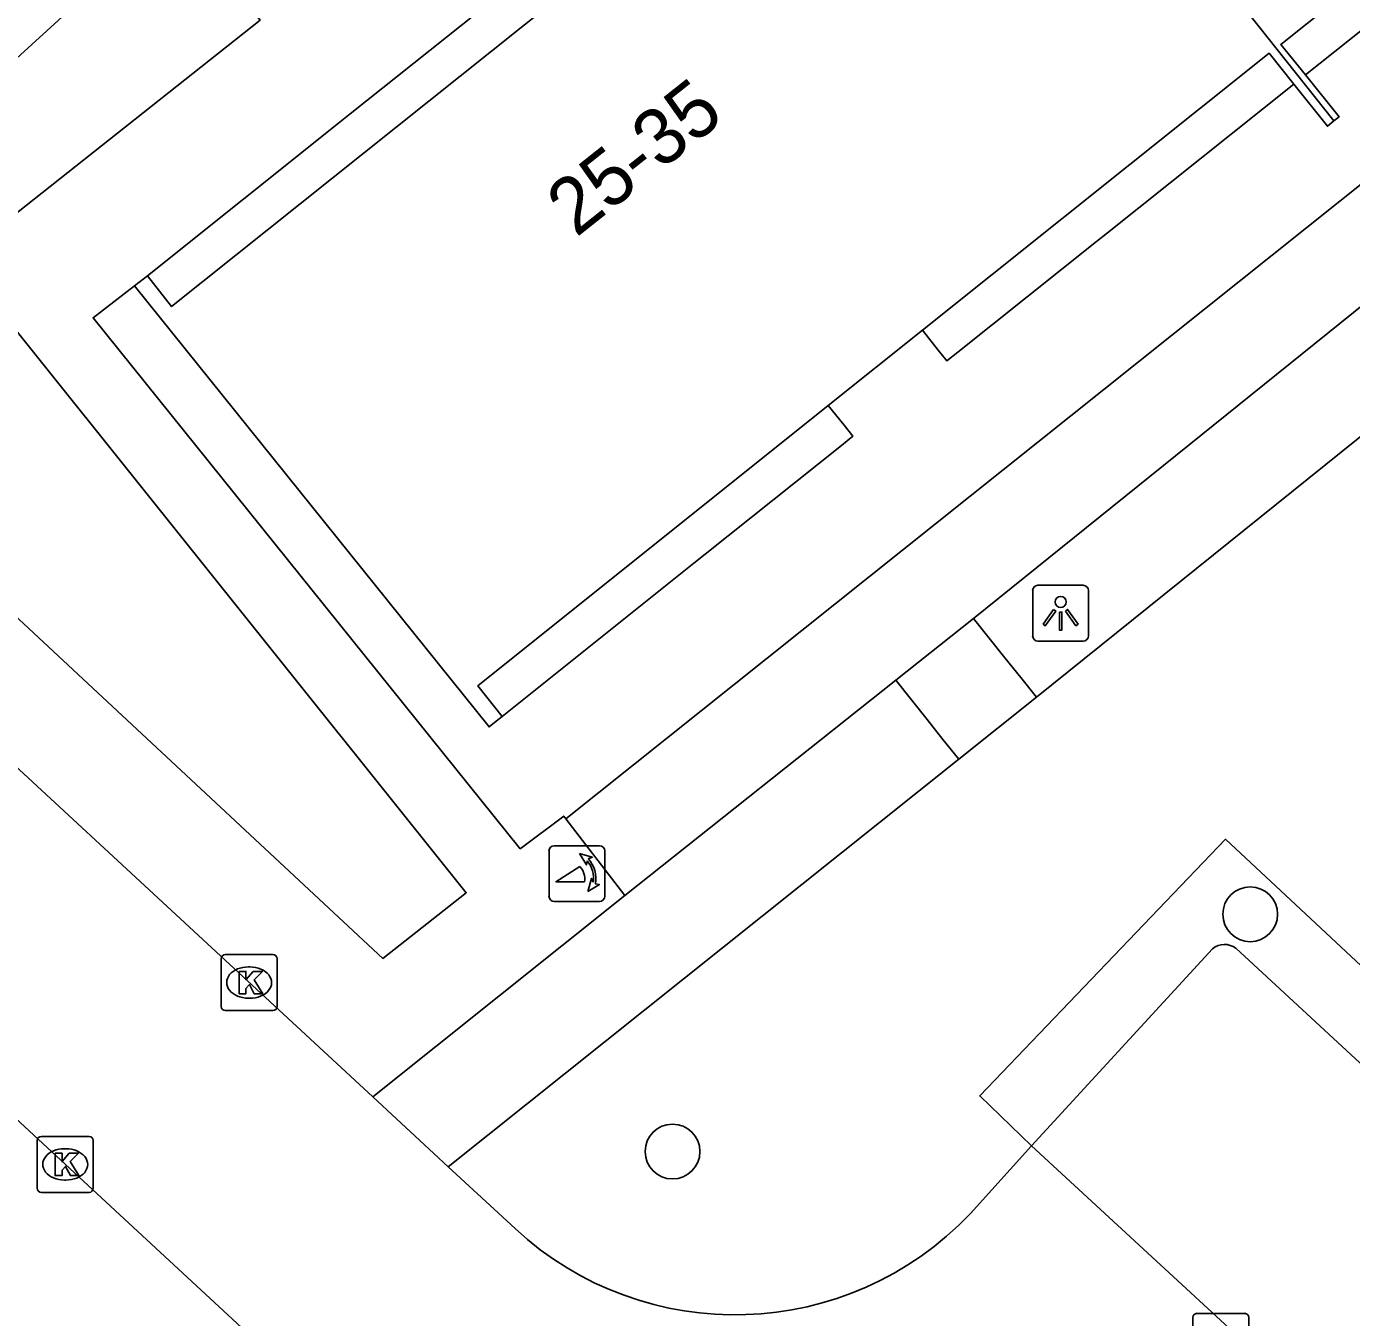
# Model space of a CAD drawing. Extents: x 159040 to 160094, y 381214 to 382518.
# Drawn here: x 159732.63 to 159756.29, y 381881.89 to 381904.94 of the extents above; entities that cross this region are included whole.
import ezdxf

# ---------------------------------------------------------------- set-up
doc = ezdxf.new("R2010")
doc.units = 0
for name, color, linetype in [('IMGEO_Boom', 7, 'Continuous'), ('IMGEO_Haag', 7, 'Continuous'), ('IMGEO_Kolk', 7, 'Continuous'), ('IMGEO_Lichtpunt', 7, 'Continuous'), ('IMGEO_Pand', 7, 'Continuous'), ('IMGEO_Pand_nummerreeks', 7, 'Continuous'), ('IMGEO_Pand_overbouw', 7, 'Continuous'), ('IMGEO_Parkeervlak_open', 7, 'Continuous'), ('IMGEO_Poller', 7, 'Continuous'), ('IMGEO_Rijbaan_lokaal_open', 7, 'Continuous'), ('IMGEO_Voetpad_gesloten', 7, 'Continuous'), ('IMGEO_Voetpad_open', 7, 'Continuous')]:
    doc.layers.add(name, color=color, linetype=linetype)

msp = doc.modelspace()

# ---------------------------------------------------------------- linework, layer by layer
at = {"layer": 'IMGEO_Boom'}
for centre in [(159754.484, 381889.092), (159744.169, 381884.857)]:
    msp.add_circle(centre, 0.489, dxfattribs=at)
at = {"layer": 'IMGEO_Haag'}
for points in [[(159763.551, 381903.327), (159750.668, 381892.968)], [(159749.281, 381891.862), (159740.163, 381884.586)], [(159767.12, 381878.228), (159754.045, 381890.43), (159749.655, 381885.849), (159750.578, 381884.958)]]:
    msp.add_lwpolyline(points, dxfattribs=at)
at = {"layer": 'IMGEO_Kolk'}
for p, q in [((159736.109, 381887.447), (159736.109, 381888.299)), ((159736.184, 381888.373), (159737.036, 381888.373)), ((159737.11, 381888.299), (159737.11, 381887.447)), ((159736.597, 381888.153), (159736.622, 381888.153)), ((159736.62, 381887.593), (159736.595, 381887.593)), ((159737.036, 381887.373), (159736.184, 381887.373)), ((159732.825, 381884.201), (159732.825, 381885.053)), ((159732.9, 381885.127), (159733.752, 381885.127)), ((159733.826, 381885.053), (159733.826, 381884.201)), ((159733.313, 381884.907), (159733.338, 381884.907)), ((159733.336, 381884.347), (159733.311, 381884.347)), ((159733.752, 381884.127), (159732.9, 381884.127)), ((159753.458, 381881.042), (159753.458, 381881.894)), ((159753.533, 381881.968), (159754.385, 381881.968)), ((159754.459, 381881.894), (159754.459, 381881.042))]:
    msp.add_line(p, q, dxfattribs=at)
for points in [[(159736.109, 381887.447), (159736.109, 381888.299)], [(159736.184, 381888.373), (159737.036, 381888.373)], [(159737.11, 381888.299), (159737.11, 381887.447)], [(159736.43, 381888.073), (159736.553, 381888.073), (159736.553, 381887.922), (159736.683, 381888.073), (159736.847, 381888.073), (159736.701, 381887.922), (159736.854, 381887.673), (159736.702, 381887.673), (159736.617, 381887.837), (159736.553, 381887.77), (159736.553, 381887.673), (159736.43, 381887.673), (159736.43, 381888.073)], [(159737.036, 381887.373), (159736.184, 381887.373)], [(159732.825, 381884.201), (159732.825, 381885.053)], [(159732.9, 381885.127), (159733.752, 381885.127)], [(159733.826, 381885.053), (159733.826, 381884.201)], [(159733.146, 381884.827), (159733.269, 381884.827), (159733.269, 381884.676), (159733.399, 381884.827), (159733.563, 381884.827), (159733.417, 381884.676), (159733.57, 381884.427), (159733.418, 381884.427), (159733.333, 381884.591), (159733.269, 381884.524), (159733.269, 381884.427), (159733.146, 381884.427), (159733.146, 381884.827)], [(159733.752, 381884.127), (159732.9, 381884.127)], [(159753.458, 381881.042), (159753.458, 381881.894)], [(159753.533, 381881.968), (159754.385, 381881.968)], [(159754.459, 381881.894), (159754.459, 381881.042)]]:
    msp.add_lwpolyline(points, dxfattribs=at)
for centre, start, end in [((159736.186, 381888.297), 91.552, 178.448), ((159736.186, 381888.297), 91.552, 178.448), ((159737.034, 381888.297), 1.552, 88.448), ((159737.034, 381888.297), 1.552, 88.448), ((159736.186, 381887.449), 181.552, 268.448), ((159736.186, 381887.449), 181.552, 268.448), ((159737.034, 381887.449), 271.552, 358.448), ((159737.034, 381887.449), 271.552, 358.448), ((159732.902, 381885.051), 91.552, 178.448), ((159732.902, 381885.051), 91.552, 178.448), ((159733.75, 381885.051), 1.552, 88.448), ((159733.75, 381885.051), 1.552, 88.448), ((159732.902, 381884.203), 181.552, 268.448), ((159732.902, 381884.203), 181.552, 268.448), ((159733.75, 381884.203), 271.552, 358.448), ((159733.75, 381884.203), 271.552, 358.448), ((159753.535, 381881.892), 91.552, 178.448), ((159753.535, 381881.892), 91.552, 178.448), ((159754.383, 381881.892), 1.552, 88.448), ((159754.383, 381881.892), 1.552, 88.448)]:
    msp.add_arc(centre, 0.0765, start, end, dxfattribs=at)
for centre, major_axis, ratio, start_param, end_param in [((159736.596, 381887.873), (-0.387, 0.002), 0.722429, 4.712389, 7.853982), ((159736.621, 381887.873), (-0.39, 0.002), 0.717154, 1.570796, 4.712389), ((159733.312, 381884.627), (-0.387, 0.002), 0.722429, 4.712389, 7.853982), ((159733.337, 381884.627), (-0.39, 0.002), 0.717154, 1.570796, 4.712389)]:
    msp.add_ellipse(centre, major_axis=major_axis, ratio=ratio, start_param=start_param, end_param=end_param, dxfattribs=at)
at = {"layer": 'IMGEO_Lichtpunt'}
for p, q in [((159750.6, 381894.87), (159750.6, 381894.063)), ((159750.6, 381894.87), (159750.6, 381894.063)), ((159751.502, 381894.965), (159750.694, 381894.965)), ((159751.502, 381894.965), (159750.694, 381894.965)), ((159751.596, 381894.063), (159751.596, 381894.87)), ((159751.596, 381894.063), (159751.596, 381894.87)), ((159750.694, 381893.969), (159751.502, 381893.969)), ((159750.694, 381893.969), (159751.502, 381893.969))]:
    msp.add_line(p, q, dxfattribs=at)
for points in [[(159750.974, 381894.534), (159751.013, 381894.506), (159750.825, 381894.244), (159750.787, 381894.271), (159750.974, 381894.534)], [(159751.076, 381894.486), (159751.123, 381894.486), (159751.123, 381894.164), (159751.076, 381894.164), (159751.076, 381894.486)], [(159751.186, 381894.506), (159751.224, 381894.533), (159751.411, 381894.271), (159751.372, 381894.243), (159751.186, 381894.506)]]:
    msp.add_lwpolyline(points, dxfattribs=at)
msp.add_circle((159751.099, 381894.668), 0.0994, dxfattribs=at)
for centre, start, end in [((159750.694, 381894.87), 90, 180), ((159750.694, 381894.87), 90, 180), ((159751.502, 381894.87), 0, 90), ((159751.502, 381894.87), 0, 90), ((159750.694, 381894.063), 180, 270), ((159750.694, 381894.063), 180, 270), ((159751.502, 381894.063), 270, 0), ((159751.502, 381894.063), 270, 360)]:
    msp.add_arc(centre, 0.0946, start, end, dxfattribs=at)
at = {"layer": 'IMGEO_Pand'}
for points in [[(159770.259, 381914.669), (159770.16, 381914.588), (159769.567, 381915.336), (159769.136, 381915.881), (159762.934, 381910.93), (159761.262, 381909.595), (159755.029, 381904.618), (159755.468, 381904.075), (159756.07, 381903.329), (159755.979, 381903.254)], [(159749.539, 381911.367), (159735.226, 381899.94), (159734.795, 381900.492), (159734.563, 381900.311)], [(159755.979, 381903.254), (159749.539, 381911.367)], [(159755.979, 381903.254), (159755.862, 381903.158), (159755.262, 381903.911), (159754.821, 381904.464), (159748.631, 381899.517), (159746.95, 381898.173), (159740.691, 381893.17), (159741.128, 381892.623), (159741.023, 381892.539), (159740.894, 381892.436), (159734.563, 381900.311)]]:
    msp.add_lwpolyline(points, dxfattribs=at)
at = {"layer": 'IMGEO_Pand_overbouw'}
for points in [[(159734.795, 381900.492), (159735.226, 381899.94), (159749.539, 381911.367), (159749.259, 381911.719), (159749.104, 381911.915), (159748.989, 381911.823), (159745.649, 381909.157), (159745.45, 381908.998), (159742.024, 381906.262), (159741.824, 381906.102), (159738.412, 381903.379), (159738.208, 381903.216)], [(159755.468, 381904.075), (159758.816, 381906.745), (159758.972, 381906.87), (159761.509, 381908.893), (159761.7, 381909.046), (159761.544, 381909.241), (159761.262, 381909.595), (159755.029, 381904.618)], [(159748.631, 381899.517), (159748.912, 381899.165), (159749.068, 381898.97), (159749.266, 381899.128), (159751.742, 381901.103), (159751.935, 381901.257), (159755.262, 381903.911), (159754.821, 381904.464)], [(159741.128, 381892.623), (159744.549, 381895.357), (159744.752, 381895.519), (159747.185, 381897.463), (159747.387, 381897.626), (159747.231, 381897.821), (159746.95, 381898.173), (159740.691, 381893.17)]]:
    msp.add_lwpolyline(points, close=True, dxfattribs=at)
at = {"layer": 'IMGEO_Parkeervlak_open'}
for points in [[(159753.812, 381888.476), (159750.578, 381884.958)], [(159758.36, 381878.369), (159761.498, 381881.763), (159754.224, 381888.485)]]:
    msp.add_lwpolyline(points, dxfattribs=at)
msp.add_arc((159754.024, 381888.22), 0.333, 52.964, 129.5388, dxfattribs=at)
at = {"layer": 'IMGEO_Poller'}
for p, q in [((159741.964, 381890.221), (159741.964, 381889.414)), ((159741.964, 381890.221), (159741.964, 381889.414)), ((159742.866, 381890.316), (159742.058, 381890.316)), ((159742.866, 381890.316), (159742.058, 381890.316)), ((159742.96, 381889.414), (159742.96, 381890.221)), ((159742.96, 381889.414), (159742.96, 381890.221)), ((159742.058, 381889.319), (159742.866, 381889.319)), ((159742.058, 381889.319), (159742.866, 381889.319))]:
    msp.add_line(p, q, dxfattribs=at)
for points in [[(159742.643, 381890.045), (159742.631, 381889.972), (159742.506, 381890.177)], [(159742.506, 381890.177), (159742.737, 381890.111), (159742.666, 381890.079)], [(159742.599, 381889.672), (159742.086, 381889.672), (159742.516, 381889.947)], [(159742.659, 381889.5), (159742.725, 381889.731), (159742.755, 381889.663)], [(159742.791, 381889.636), (159742.863, 381889.625), (159742.659, 381889.5)]]:
    msp.add_lwpolyline(points, dxfattribs=at)
for centre, radius, start, end in [((159742.058, 381890.221), 0.0946, 90, 180), ((159742.058, 381890.221), 0.0946, 90, 180), ((159742.866, 381890.221), 0.0946, 0, 90), ((159742.866, 381890.221), 0.0946, 0, 90), ((159742.271, 381889.722), 0.332, 351.3247, 42.4854), ((159742.285, 381889.732), 0.476, 351.7527, 41.1691), ((159742.285, 381889.732), 0.516, 349.3569, 42.2912), ((159742.058, 381889.414), 0.0946, 180, 270), ((159742.058, 381889.414), 0.0946, 180, 270), ((159742.866, 381889.414), 0.0946, 270, 0), ((159742.866, 381889.414), 0.0946, 270, 0)]:
    msp.add_arc(centre, radius, start, end, dxfattribs=at)
at = {"layer": 'IMGEO_Rijbaan_lokaal_open'}
for points in [[(159738.817, 381885.832), (159726.824, 381896.926)], [(159723.801, 381893.444), (159745.268, 381873.571)], [(159740.163, 381884.586), (159739.907, 381884.824), (159739.573, 381885.132), (159739.239, 381885.441), (159738.817, 381885.832)], [(159750.578, 381884.958), (159749.488, 381883.751)], [(159750.578, 381884.958), (159758.409, 381877.735)], [(159741.358, 381883.482), (159740.163, 381884.586)]]:
    msp.add_lwpolyline(points, dxfattribs=at)
msp.add_arc((159745.287, 381887.724), 5.782, 227.1911, 316.5991, dxfattribs=at)
at = {"layer": 'IMGEO_Voetpad_gesloten'}
for points in [[(159815.494, 381899.569), (159788.392, 381924.64), (159784.932, 381924.842), (159742.264, 381890.796)], [(159749.542, 381894.374), (159762.408, 381904.732)], [(159748.154, 381893.269), (159749.542, 381894.374)], [(159743.32, 381889.426), (159748.154, 381893.269)], [(159742.264, 381890.796), (159743.32, 381889.426)]]:
    msp.add_lwpolyline(points, dxfattribs=at)
at = {"layer": 'IMGEO_Voetpad_open'}
for points in [[(159735.282, 381906.952), (159736.807, 381905.056), (159731.419, 381900.793), (159740.485, 381889.477), (159738.999, 381888.305), (159727.928, 381898.616), (159729.499, 381901.679)], [(159729.499, 381901.679), (159735.282, 381906.952)], [(159734.563, 381900.311), (159733.825, 381899.74), (159741.452, 381890.263), (159742.226, 381890.845), (159742.264, 381890.796)], [(159750.668, 381892.968), (159750.386, 381893.321), (159750.104, 381893.672), (159749.823, 381894.023), (159749.542, 381894.374)], [(159748.154, 381893.269), (159748.435, 381892.918), (159748.717, 381892.567), (159748.998, 381892.215), (159749.281, 381891.862)], [(159750.668, 381892.968), (159749.281, 381891.862)], [(159743.32, 381889.426), (159738.817, 381885.832)]]:
    msp.add_lwpolyline(points, dxfattribs=at)

# ---------------------------------------------------------------- texts
at = {"layer": 'IMGEO_Pand_nummerreeks'}
msp.add_text('25-35', height=1, rotation=38.4455, dxfattribs=at).set_placement((159742.449, 381901.164))

doc.saveas('drawing.dxf')
